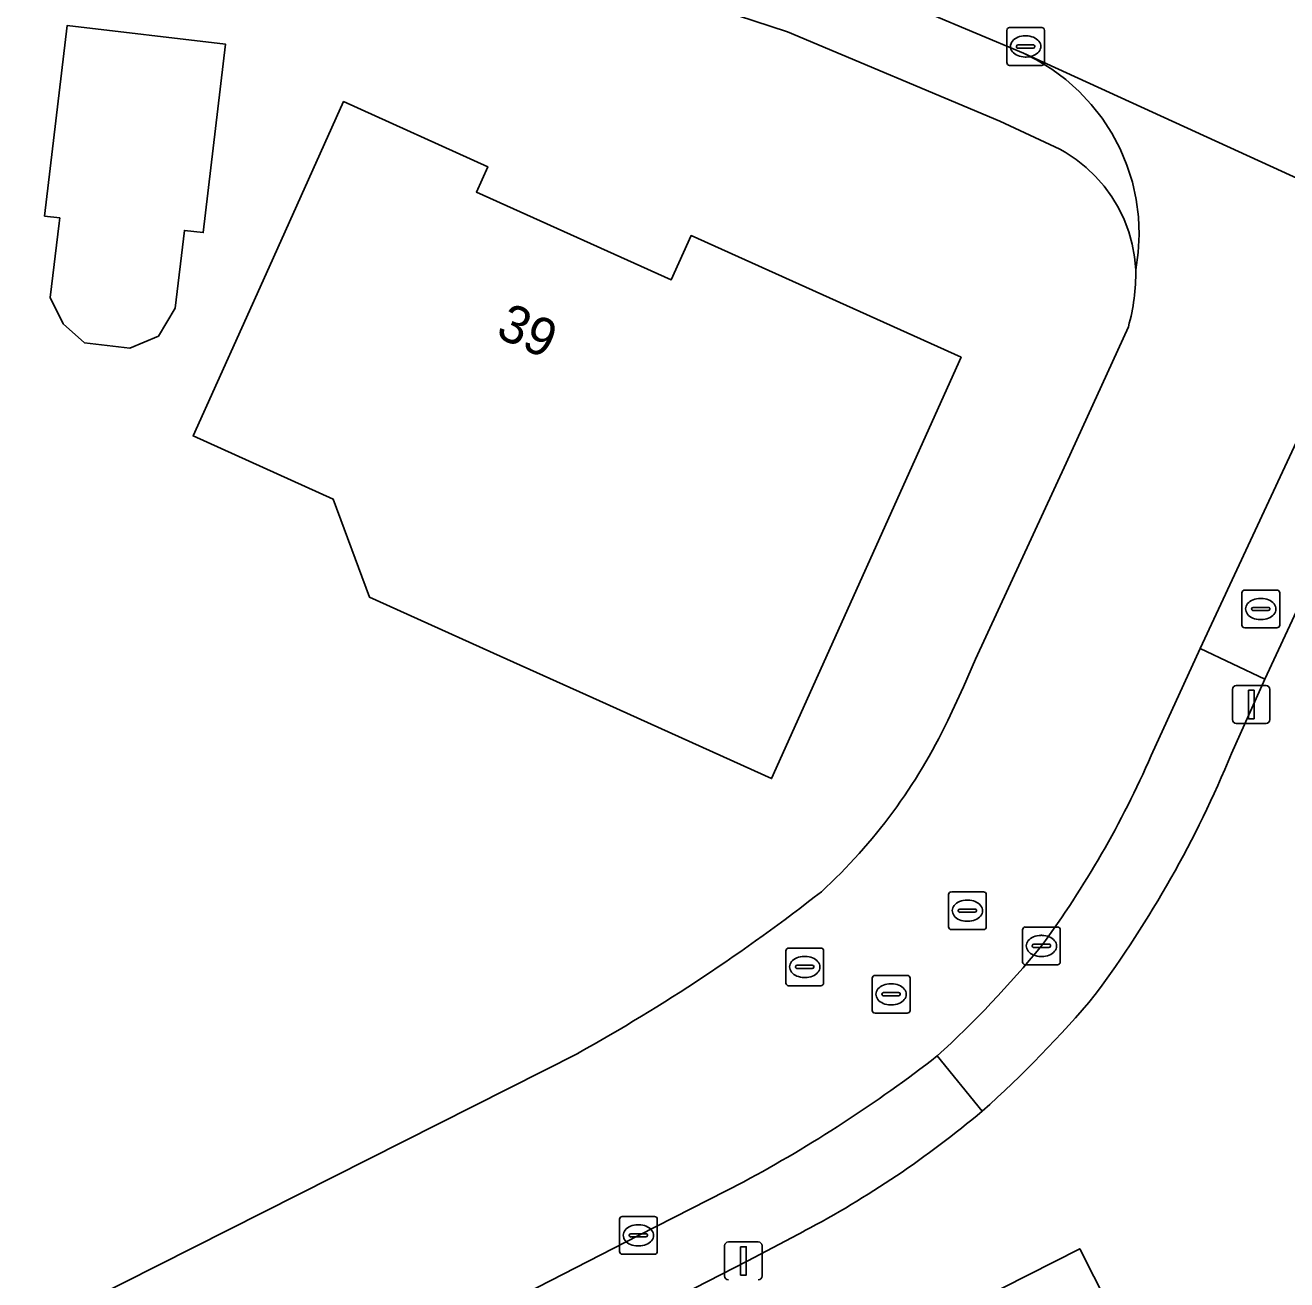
# Model space of a CAD drawing. Extents: x 162722 to 165104, y 384719 to 386284.
# Drawn here: x 164010.37 to 164043.76, y 385136.68 to 385169.88 of the extents above; entities that cross this region are included whole.
import ezdxf

# ---------------------------------------------------------------- set-up
doc = ezdxf.new("R2010")
doc.units = 0
for name, color, linetype in [('IMGEO_Brandkraan', 7, 'Continuous'), ('IMGEO_Erf', 7, 'Continuous'), ('IMGEO_Kolk', 7, 'Continuous'), ('IMGEO_Lichtmast', 7, 'Continuous'), ('IMGEO_Pand', 7, 'Continuous'), ('IMGEO_Pand_nummerreeks', 7, 'Continuous'), ('IMGEO_Parkeervlak_open', 7, 'Continuous'), ('IMGEO_Rijbaan_lokaal_gesloten', 7, 'Continuous'), ('IMGEO_Rioolput', 7, 'Continuous'), ('IMGEO_Voetpad_open', 7, 'Continuous')]:
    doc.layers.add(name, color=color, linetype=linetype)

msp = doc.modelspace()

# ---------------------------------------------------------------- linework, layer by layer
at = {"layer": 'IMGEO_Brandkraan'}
for p, q in [((164042.576, 385154.006), (164042.576, 385154.858)), ((164042.651, 385154.932), (164043.503, 385154.932)), ((164043.064, 385154.712), (164043.089, 385154.712)), ((164043.577, 385154.858), (164043.577, 385154.006)), ((164042.835, 385154.426), (164042.835, 385154.438)), ((164043.273, 385154.389), (164042.875, 385154.389)), ((164042.878, 385154.475), (164043.276, 385154.475)), ((164043.319, 385154.438), (164043.319, 385154.426)), ((164043.087, 385154.152), (164043.062, 385154.152)), ((164043.503, 385153.932), (164042.651, 385153.932))]:
    msp.add_line(p, q, dxfattribs=at)
for points in [[(164042.576, 385154.006), (164042.576, 385154.858)], [(164042.651, 385154.932), (164043.503, 385154.932)], [(164043.577, 385154.858), (164043.577, 385154.006)], [(164043.503, 385153.932), (164042.651, 385153.932)]]:
    msp.add_lwpolyline(points, dxfattribs=at)
for centre, radius, start, end in [((164042.653, 385154.856), 0.0765, 91.552, 178.448), ((164042.653, 385154.856), 0.0765, 91.552, 178.448), ((164043.501, 385154.856), 0.0765, 1.552, 88.448), ((164043.501, 385154.856), 0.0765, 1.552, 88.448), ((164042.875, 385154.435), 0.0403, 85.8775, 175.7526), ((164042.872, 385154.425), 0.0366, 178.938, 274.7102), ((164043.276, 385154.432), 0.043, 264.8664, 352.4533), ((164043.28, 385154.437), 0.0386, 1.7309, 96.639), ((164042.653, 385154.008), 0.0765, 181.552, 268.448), ((164042.653, 385154.008), 0.0765, 181.552, 268.448), ((164043.501, 385154.008), 0.0765, 271.552, 358.448), ((164043.501, 385154.008), 0.0765, 271.552, 358.448)]:
    msp.add_arc(centre, radius, start, end, dxfattribs=at)
for centre, major_axis, ratio, start_param, end_param in [((164043.063, 385154.432), (-0.387, 0.002), 0.722429, 4.712389, 7.853982), ((164043.088, 385154.432), (-0.39, 0.002), 0.717154, 1.570796, 4.712389)]:
    msp.add_ellipse(centre, major_axis=major_axis, ratio=ratio, start_param=start_param, end_param=end_param, dxfattribs=at)
at = {"layer": 'IMGEO_Erf'}
for points in [[(164039.766, 385163.405), (164039.734, 385163.747), (164039.672, 385164.085), (164039.579, 385164.415), (164039.458, 385164.737), (164039.308, 385165.046), (164039.132, 385165.34), (164038.929, 385165.618), (164038.703, 385165.876), (164038.455, 385166.113), (164038.186, 385166.327), (164037.899, 385166.516), (164037.754, 385166.599), (164036.166, 385167.339), (164030.547, 385169.706), (164025.714, 385171.29)], [(164037.924, 385158.288), (164039.57, 385161.899)], [(164045.884, 385158.374), (164043.183, 385152.572), (164042.299, 385150.607)], [(164034.788, 385151.483), (164035.203, 385152.376), (164035.523, 385153.106), (164037.924, 385158.288)], [(163964.943, 385112.381), (164000, 385130.066), (164025.009, 385142.682)], [(164030.99, 385137.973), (164029.497, 385137.184), (164022.8, 385133.757), (164016.911, 385130.797), (164003.318, 385123.864), (164000, 385122.177), (163997.359, 385120.835), (163983.951, 385114.019)], [(164034.886, 385135.784), (164038.282, 385137.505), (164041.28, 385131.592)]]:
    msp.add_lwpolyline(points, dxfattribs=at)
for points in [[(164011.371, 385161.981), (164011.029, 385162.678), (164011.262, 385164.644), (164011.278, 385164.781), (164010.878, 385164.828), (164011.477, 385169.873), (164015.672, 385169.375), (164015.08, 385164.39), (164014.581, 385164.449), (164014.337, 385162.39), (164013.891, 385161.655), (164013.131, 385161.334), (164011.938, 385161.476)], [(164019.476, 385154.742), (164018.52, 385157.342), (164014.811, 385159.012), (164016.741, 385163.298), (164018.794, 385167.856), (164022.613, 385166.136), (164022.31, 385165.462), (164027.465, 385163.141), (164027.993, 385164.312), (164035.144, 385161.091), (164030.125, 385149.945), (164025.567, 385151.998), (164022.941, 385153.181)]]:
    msp.add_lwpolyline(points, close=True, dxfattribs=at)
for centre, radius, start, end in [((164034.63, 385163.308), 5.137, 344.084, 1.0857), ((164021.408, 385157.859), 14.822, 312.6206, 334.5227), ((164015.003, 385161.83), 29.513, 323.3909, 337.649), ((164000.745, 385186.232), 49.853, 299.1242, 308.009), ((164016.769, 385162.514), 28.549, 311.5413, 320.1745), ((164018.634, 385161.403), 26.488, 297.8066, 310.1163)]:
    msp.add_arc(centre, radius, start, end, dxfattribs=at)
at = {"layer": 'IMGEO_Kolk'}
for p, q in [((164036.351, 385168.891), (164036.351, 385169.743)), ((164036.426, 385169.817), (164037.278, 385169.817)), ((164037.352, 385169.743), (164037.352, 385168.891)), ((164036.653, 385169.36), (164037.051, 385169.36)), ((164036.839, 385169.597), (164036.864, 385169.597)), ((164036.61, 385169.311), (164036.61, 385169.323)), ((164037.048, 385169.274), (164036.65, 385169.274)), ((164036.862, 385169.037), (164036.837, 385169.037)), ((164037.094, 385169.323), (164037.094, 385169.311)), ((164037.278, 385168.817), (164036.426, 385168.817)), ((164036.843, 385146.017), (164037.695, 385146.017)), ((164036.768, 385145.091), (164036.768, 385145.943)), ((164037.256, 385145.797), (164037.281, 385145.797)), ((164037.769, 385145.943), (164037.769, 385145.091)), ((164037.027, 385145.511), (164037.027, 385145.523)), ((164037.465, 385145.474), (164037.067, 385145.474)), ((164037.07, 385145.56), (164037.468, 385145.56)), ((164037.511, 385145.523), (164037.511, 385145.511)), ((164037.695, 385145.017), (164036.843, 385145.017)), ((164037.279, 385145.237), (164037.254, 385145.237)), ((164026.098, 385137.432), (164026.098, 385138.284)), ((164026.173, 385138.358), (164027.025, 385138.358)), ((164027.099, 385138.284), (164027.099, 385137.432)), ((164026.586, 385138.138), (164026.611, 385138.138)), ((164026.357, 385137.852), (164026.357, 385137.864)), ((164026.795, 385137.815), (164026.397, 385137.815)), ((164026.4, 385137.901), (164026.798, 385137.901)), ((164026.841, 385137.864), (164026.841, 385137.852)), ((164027.025, 385137.358), (164026.173, 385137.358)), ((164026.609, 385137.578), (164026.584, 385137.578))]:
    msp.add_line(p, q, dxfattribs=at)
for points in [[(164036.351, 385168.891), (164036.351, 385169.743)], [(164036.426, 385169.817), (164037.278, 385169.817)], [(164037.352, 385169.743), (164037.352, 385168.891)], [(164037.278, 385168.817), (164036.426, 385168.817)], [(164036.843, 385146.017), (164037.695, 385146.017)], [(164036.768, 385145.091), (164036.768, 385145.943)], [(164037.769, 385145.943), (164037.769, 385145.091)], [(164037.695, 385145.017), (164036.843, 385145.017)], [(164026.098, 385137.432), (164026.098, 385138.284)], [(164026.173, 385138.358), (164027.025, 385138.358)], [(164027.099, 385138.284), (164027.099, 385137.432)], [(164027.025, 385137.358), (164026.173, 385137.358)]]:
    msp.add_lwpolyline(points, dxfattribs=at)
for centre, radius, start, end in [((164036.428, 385169.741), 0.0765, 91.552, 178.448), ((164036.428, 385169.741), 0.0765, 91.552, 178.448), ((164037.276, 385169.741), 0.0765, 1.552, 88.448), ((164037.276, 385169.741), 0.0765, 1.552, 88.448), ((164036.65, 385169.32), 0.0403, 85.8775, 175.7526), ((164037.055, 385169.322), 0.0386, 1.7309, 96.639), ((164036.647, 385169.31), 0.0366, 178.938, 274.7102), ((164037.051, 385169.317), 0.043, 264.8664, 352.4533), ((164036.428, 385168.893), 0.0765, 181.552, 268.448), ((164036.428, 385168.893), 0.0765, 181.552, 268.448), ((164037.276, 385168.893), 0.0765, 271.552, 358.448), ((164037.276, 385168.893), 0.0765, 271.552, 358.448), ((164036.845, 385145.941), 0.0765, 91.552, 178.448), ((164036.845, 385145.941), 0.0765, 91.552, 178.448), ((164037.693, 385145.941), 0.0765, 1.552, 88.448), ((164037.693, 385145.941), 0.0765, 1.552, 88.448), ((164037.067, 385145.52), 0.0403, 85.8775, 175.7526), ((164037.064, 385145.51), 0.0366, 178.938, 274.7102), ((164037.468, 385145.517), 0.043, 264.8664, 352.4533), ((164037.472, 385145.522), 0.0386, 1.7309, 96.639), ((164036.845, 385145.093), 0.0765, 181.552, 268.448), ((164036.845, 385145.093), 0.0765, 181.552, 268.448), ((164037.693, 385145.093), 0.0765, 271.552, 358.448), ((164037.693, 385145.093), 0.0765, 271.552, 358.448), ((164026.175, 385138.282), 0.0765, 91.552, 178.448), ((164026.175, 385138.282), 0.0765, 91.552, 178.448), ((164027.023, 385138.282), 0.0765, 1.552, 88.448), ((164027.023, 385138.282), 0.0765, 1.552, 88.448), ((164026.397, 385137.861), 0.0403, 85.8775, 175.7526), ((164026.394, 385137.851), 0.0366, 178.938, 274.7102), ((164026.798, 385137.858), 0.043, 264.8664, 352.4533), ((164026.802, 385137.863), 0.0386, 1.7309, 96.639), ((164026.175, 385137.434), 0.0765, 181.552, 268.448), ((164026.175, 385137.434), 0.0765, 181.552, 268.448), ((164027.023, 385137.434), 0.0765, 271.552, 358.448), ((164027.023, 385137.434), 0.0765, 271.552, 358.448)]:
    msp.add_arc(centre, radius, start, end, dxfattribs=at)
for centre, major_axis, ratio, start_param, end_param in [((164036.838, 385169.317), (-0.387, 0.002), 0.722429, 4.712389, 7.853982), ((164036.863, 385169.317), (-0.39, 0.002), 0.717154, 1.570796, 4.712389), ((164037.255, 385145.517), (-0.387, 0.002), 0.722429, 4.712389, 7.853982), ((164037.28, 385145.517), (-0.39, 0.002), 0.717154, 1.570796, 4.712389), ((164026.585, 385137.858), (-0.387, 0.002), 0.722429, 4.712389, 7.853982), ((164026.61, 385137.858), (-0.39, 0.002), 0.717154, 1.570796, 4.712389)]:
    msp.add_ellipse(centre, major_axis=major_axis, ratio=ratio, start_param=start_param, end_param=end_param, dxfattribs=at)
at = {"layer": 'IMGEO_Lichtmast'}
for p, q in [((164042.427, 385152.405), (164043.217, 385152.405)), ((164043.217, 385152.405), (164042.427, 385152.405)), ((164042.327, 385151.505), (164042.327, 385152.305)), ((164042.327, 385152.305), (164042.327, 385151.505)), ((164043.317, 385152.305), (164043.317, 385151.505)), ((164043.317, 385151.505), (164043.317, 385152.305)), ((164043.217, 385151.405), (164042.427, 385151.405)), ((164042.427, 385151.405), (164043.217, 385151.405)), ((164028.983, 385137.683), (164029.773, 385137.683)), ((164029.773, 385137.683), (164028.983, 385137.683)), ((164028.883, 385136.783), (164028.883, 385137.583)), ((164028.883, 385137.583), (164028.883, 385136.783)), ((164029.873, 385137.583), (164029.873, 385136.783)), ((164029.873, 385136.783), (164029.873, 385137.583))]:
    msp.add_line(p, q, dxfattribs=at)
for points in [[(164042.747, 385152.28), (164042.897, 385152.28), (164042.897, 385151.53), (164042.747, 385151.53), (164042.747, 385152.28)], [(164029.303, 385137.558), (164029.453, 385137.558), (164029.453, 385136.808), (164029.303, 385136.808), (164029.303, 385137.558)]]:
    msp.add_lwpolyline(points, dxfattribs=at)
for centre, start, end in [((164042.427, 385152.305), 90, 180), ((164042.427, 385152.305), 90, 180), ((164043.217, 385152.305), 0, 90), ((164043.217, 385152.305), 360, 90), ((164042.427, 385151.505), 180, 270), ((164042.427, 385151.505), 180, 270), ((164043.217, 385151.505), 270, 0), ((164043.217, 385151.505), 270, 0), ((164028.983, 385137.583), 90, 180), ((164028.983, 385137.583), 90, 180), ((164029.773, 385137.583), 0, 90), ((164029.773, 385137.583), 360, 90), ((164028.983, 385136.783), 180, 270), ((164028.983, 385136.783), 180, 270), ((164029.773, 385136.783), 270, 0), ((164029.773, 385136.783), 270, 0)]:
    msp.add_arc(centre, 0.1, start, end, dxfattribs=at)
at = {"layer": 'IMGEO_Pand'}
for points in [[(164014.337, 385162.39), (164014.581, 385164.449), (164015.08, 385164.39), (164015.672, 385169.375), (164011.477, 385169.873), (164010.878, 385164.828), (164011.278, 385164.781), (164011.262, 385164.644), (164011.029, 385162.678), (164011.371, 385161.981), (164011.938, 385161.476), (164013.131, 385161.334), (164013.891, 385161.655)], [(164014.811, 385159.012), (164018.52, 385157.342), (164019.476, 385154.742), (164022.941, 385153.181), (164025.567, 385151.998), (164030.125, 385149.945), (164035.144, 385161.091), (164027.993, 385164.312), (164027.465, 385163.141), (164022.31, 385165.462), (164022.613, 385166.136), (164018.794, 385167.856), (164016.741, 385163.298)], [(164035.656, 385125.488), (164038.981, 385127.174), (164041.012, 385123.168), (164047.513, 385126.465), (164046.431, 385128.599), (164044.171, 385133.058), (164041.28, 385131.592), (164038.282, 385137.505), (164034.886, 385135.784), (164034.573, 385136.401), (164031.033, 385134.606)]]:
    msp.add_lwpolyline(points, close=True, dxfattribs=at)
at = {"layer": 'IMGEO_Parkeervlak_open'}
msp.add_lwpolyline([(164025.714, 385171.29), (164030.547, 385169.706), (164036.166, 385167.339), (164037.754, 385166.599), (164037.899, 385166.516), (164038.186, 385166.327), (164038.455, 385166.113), (164038.703, 385165.876), (164038.929, 385165.618), (164039.132, 385165.34), (164039.308, 385165.046), (164039.458, 385164.737), (164039.579, 385164.415), (164039.672, 385164.085), (164039.734, 385163.747), (164039.766, 385163.405), (164039.832, 385163.869), (164039.855, 385164.338), (164039.837, 385164.806), (164039.777, 385165.271), (164039.676, 385165.729), (164039.534, 385166.176), (164039.353, 385166.608), (164039.134, 385167.023), (164038.879, 385167.416), (164038.59, 385167.785), (164038.269, 385168.127), (164037.919, 385168.439), (164037.542, 385168.718), (164037.142, 385168.962), (164036.795, 385169.137), (164031.751, 385171.269)], dxfattribs=at)
at = {"layer": 'IMGEO_Rijbaan_lokaal_gesloten'}
for points in [[(163946.345, 385182.337), (163959.871, 385181.283), (163961.537, 385181.086), (163975.917, 385179.858), (163980.657, 385179.445), (163982.043, 385179.328), (164000, 385177.774), (164001.089, 385177.667), (164003.306, 385177.464), (164006.878, 385177.162), (164011.653, 385176.534), (164019.703, 385174.889), (164019.892, 385174.859), (164021.592, 385174.502), (164023.254, 385173.995), (164026.265, 385173.125), (164031.751, 385171.269), (164036.795, 385169.137), (164051.9, 385162.23), (164052.042, 385162.153), (164054.177, 385161.165), (164066.085, 385155.714)], [(164052.042, 385162.153), (164051.9, 385162.23), (164036.795, 385169.137), (164037.142, 385168.962), (164037.542, 385168.718), (164037.919, 385168.439), (164038.269, 385168.127), (164038.59, 385167.785), (164038.879, 385167.416), (164039.134, 385167.023), (164039.353, 385166.608), (164039.534, 385166.176), (164039.676, 385165.729), (164039.777, 385165.271), (164039.837, 385164.806), (164039.855, 385164.338), (164039.832, 385163.869), (164039.766, 385163.405)], [(164039.57, 385161.899), (164037.924, 385158.288), (164035.523, 385153.106), (164035.203, 385152.376), (164034.788, 385151.483)], [(164040.174, 385150.554), (164041.473, 385153.384), (164044.201, 385159.231), (164044.452, 385159.725)], [(164025.009, 385142.682), (164000, 385130.066), (163964.943, 385112.381), (163967.315, 385107.723), (163976.438, 385112.369), (163976.92, 385112.606), (163983.085, 385115.734), (163989.577, 385119.038), (163996.493, 385122.545), (164000, 385124.341), (164000.916, 385124.81), (164002.466, 385125.576), (164013.005, 385130.942)], [(164013.005, 385130.942), (164016.077, 385132.488), (164021.941, 385135.467), (164026.599, 385137.858), (164029.39, 385139.278)]]:
    msp.add_lwpolyline(points, dxfattribs=at)
for centre, radius, start, end in [((164034.63, 385163.308), 5.137, 344.084, 1.0857), ((164021.408, 385157.859), 14.822, 312.6206, 334.5227), ((164016.372, 385160.925), 25.963, 323.5972, 336.4559), ((164000.745, 385186.232), 49.853, 299.1242, 308.009), ((164016.153, 385162.773), 27.27, 312.3052, 320.7442), ((164012.194, 385171.33), 36.374, 298.2128, 307.8397)]:
    msp.add_arc(centre, radius, start, end, dxfattribs=at)
at = {"layer": 'IMGEO_Rioolput'}
for p, q in [((164034.809, 385146.023), (164034.809, 385146.875)), ((164034.884, 385146.949), (164035.736, 385146.949)), ((164035.297, 385146.729), (164035.322, 385146.729)), ((164035.81, 385146.875), (164035.81, 385146.023)), ((164035.068, 385146.443), (164035.068, 385146.455)), ((164035.506, 385146.406), (164035.108, 385146.406)), ((164035.111, 385146.492), (164035.509, 385146.492)), ((164035.552, 385146.455), (164035.552, 385146.443)), ((164035.32, 385146.169), (164035.295, 385146.169)), ((164035.736, 385145.949), (164034.884, 385145.949)), ((164030.502, 385144.535), (164030.502, 385145.387)), ((164030.577, 385145.461), (164031.429, 385145.461)), ((164031.503, 385145.387), (164031.503, 385144.535)), ((164030.761, 385144.955), (164030.761, 385144.967)), ((164030.804, 385145.004), (164031.202, 385145.004)), ((164030.99, 385145.241), (164031.015, 385145.241)), ((164031.245, 385144.967), (164031.245, 385144.955)), ((164031.199, 385144.918), (164030.801, 385144.918)), ((164031.013, 385144.681), (164030.988, 385144.681)), ((164032.789, 385143.811), (164032.789, 385144.663)), ((164032.864, 385144.737), (164033.716, 385144.737)), ((164033.79, 385144.663), (164033.79, 385143.811)), ((164031.429, 385144.461), (164030.577, 385144.461)), ((164033.277, 385144.517), (164033.302, 385144.517)), ((164033.048, 385144.231), (164033.048, 385144.243)), ((164033.486, 385144.194), (164033.088, 385144.194)), ((164033.091, 385144.28), (164033.489, 385144.28)), ((164033.532, 385144.243), (164033.532, 385144.231)), ((164033.716, 385143.737), (164032.864, 385143.737)), ((164033.3, 385143.957), (164033.275, 385143.957))]:
    msp.add_line(p, q, dxfattribs=at)
for points in [[(164034.809, 385146.023), (164034.809, 385146.875)], [(164034.884, 385146.949), (164035.736, 385146.949)], [(164035.81, 385146.875), (164035.81, 385146.023)], [(164035.736, 385145.949), (164034.884, 385145.949)], [(164030.502, 385144.535), (164030.502, 385145.387)], [(164030.577, 385145.461), (164031.429, 385145.461)], [(164031.503, 385145.387), (164031.503, 385144.535)], [(164032.789, 385143.811), (164032.789, 385144.663)], [(164032.864, 385144.737), (164033.716, 385144.737)], [(164033.79, 385144.663), (164033.79, 385143.811)], [(164031.429, 385144.461), (164030.577, 385144.461)], [(164033.716, 385143.737), (164032.864, 385143.737)]]:
    msp.add_lwpolyline(points, dxfattribs=at)
for centre, radius, start, end in [((164034.886, 385146.873), 0.0765, 91.552, 178.448), ((164034.886, 385146.873), 0.0765, 91.552, 178.448), ((164035.734, 385146.873), 0.0765, 1.552, 88.448), ((164035.734, 385146.873), 0.0765, 1.552, 88.448), ((164035.108, 385146.452), 0.0403, 85.8775, 175.7526), ((164035.105, 385146.442), 0.0366, 178.938, 274.7102), ((164035.509, 385146.449), 0.043, 264.8664, 352.4533), ((164035.513, 385146.454), 0.0386, 1.7309, 96.639), ((164034.886, 385146.025), 0.0765, 181.552, 268.448), ((164034.886, 385146.025), 0.0765, 181.552, 268.448), ((164035.734, 385146.025), 0.0765, 271.552, 358.448), ((164035.734, 385146.025), 0.0765, 271.552, 358.448), ((164030.579, 385145.385), 0.0765, 91.552, 178.448), ((164030.579, 385145.385), 0.0765, 91.552, 178.448), ((164031.427, 385145.385), 0.0765, 1.552, 88.448), ((164031.427, 385145.385), 0.0765, 1.552, 88.448), ((164030.801, 385144.964), 0.0403, 85.8775, 175.7526), ((164031.206, 385144.966), 0.0386, 1.7309, 96.639), ((164030.798, 385144.954), 0.0366, 178.938, 274.7102), ((164031.202, 385144.961), 0.043, 264.8664, 352.4533), ((164032.866, 385144.661), 0.0765, 91.552, 178.448), ((164032.866, 385144.661), 0.0765, 91.552, 178.448), ((164033.714, 385144.661), 0.0765, 1.552, 88.448), ((164033.714, 385144.661), 0.0765, 1.552, 88.448), ((164030.579, 385144.537), 0.0765, 181.552, 268.448), ((164030.579, 385144.537), 0.0765, 181.552, 268.448), ((164031.427, 385144.537), 0.0765, 271.552, 358.448), ((164031.427, 385144.537), 0.0765, 271.552, 358.448), ((164033.088, 385144.24), 0.0403, 85.8775, 175.7526), ((164033.085, 385144.23), 0.0366, 178.938, 274.7102), ((164033.489, 385144.237), 0.043, 264.8664, 352.4533), ((164033.493, 385144.242), 0.0386, 1.7309, 96.639), ((164032.866, 385143.813), 0.0765, 181.552, 268.448), ((164032.866, 385143.813), 0.0765, 181.552, 268.448), ((164033.714, 385143.813), 0.0765, 271.552, 358.448), ((164033.714, 385143.813), 0.0765, 271.552, 358.448)]:
    msp.add_arc(centre, radius, start, end, dxfattribs=at)
for centre, major_axis, ratio, start_param, end_param in [((164035.296, 385146.449), (-0.387, 0.002), 0.722429, 4.712389, 7.853982), ((164035.321, 385146.449), (-0.39, 0.002), 0.717154, 1.570796, 4.712389), ((164030.989, 385144.961), (-0.387, 0.002), 0.722429, 4.712389, 7.853982), ((164031.014, 385144.961), (-0.39, 0.002), 0.717154, 1.570796, 4.712389), ((164033.276, 385144.237), (-0.387, 0.002), 0.722429, 4.712389, 7.853982), ((164033.301, 385144.237), (-0.39, 0.002), 0.717154, 1.570796, 4.712389)]:
    msp.add_ellipse(centre, major_axis=major_axis, ratio=ratio, start_param=start_param, end_param=end_param, dxfattribs=at)
at = {"layer": 'IMGEO_Voetpad_open'}
msp.add_lwpolyline([(164043.183, 385152.572), (164045.884, 385158.374), (164044.201, 385159.231), (164041.473, 385153.384)], close=True, dxfattribs=at)
for points in [[(164042.299, 385150.607), (164043.183, 385152.572), (164041.473, 385153.384), (164040.174, 385150.554)], [(164035.701, 385141.146), (164034.508, 385142.605)], [(164034.508, 385142.605), (164035.701, 385141.146)], [(164029.39, 385139.278), (164026.599, 385137.858), (164021.941, 385135.467), (164022.8, 385133.757), (164029.497, 385137.184), (164030.99, 385137.973)]]:
    msp.add_lwpolyline(points, dxfattribs=at)
for centre, radius, start, end in [((164016.372, 385160.925), 25.963, 323.5972, 336.4559), ((164015.003, 385161.83), 29.513, 323.3909, 337.649), ((164016.153, 385162.773), 27.27, 312.3052, 320.7442), ((164016.769, 385162.514), 28.549, 311.5413, 320.1745), ((164012.194, 385171.33), 36.374, 298.2128, 307.8397), ((164018.634, 385161.403), 26.488, 297.8066, 310.1163)]:
    msp.add_arc(centre, radius, start, end, dxfattribs=at)

# ---------------------------------------------------------------- texts
at = {"layer": 'IMGEO_Pand_nummerreeks'}
msp.add_text('39', height=1, rotation=335.7607, dxfattribs=at).set_placement((164022.788, 385161.65))

doc.saveas('drawing.dxf')
